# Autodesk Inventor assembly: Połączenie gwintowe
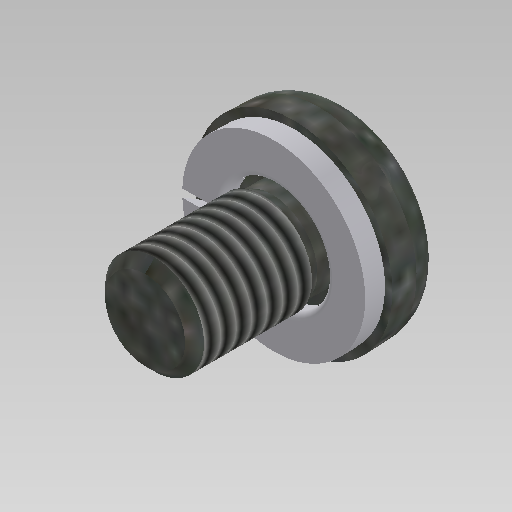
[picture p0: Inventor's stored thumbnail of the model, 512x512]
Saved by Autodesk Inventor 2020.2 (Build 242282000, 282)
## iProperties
Manager: www.cadconsulting.pl
Company: Fabian Stasiak CAD Consulting
ClientObjectVersion: 1
Created: 2019-11
Part Number: Połączenie gwintowe
Document SubType Name: Assembly
Designer: F.Stasiak
Author: F.Stasiak
Subject: Zbiór ćwiczeń. Autodesk Inventor 2020. Kurs podstawowy
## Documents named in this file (3)
- C:\2020_Kurs_podstawowy\R6 Zespoły\BOM\123-000-000\Design Accelerator\Połączenie gwintowe3.iam
- C:\2020_Kurs_podstawowy\Zasoby\Content Center Files\pl-PL\DIN 128\DIN 128 - A8.ipt
- C:\2020_Kurs_podstawowy\Zasoby\Content Center Files\pl-PL\ISO 7045  H\ISO 7045 - M8 x 12 - 4.8 - H - ISO.ipt
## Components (2 placed, 2 different names)
1. DIN 128 A8:1
2. ISO 7045 H M8 x 12 - 4.8 - H:1
